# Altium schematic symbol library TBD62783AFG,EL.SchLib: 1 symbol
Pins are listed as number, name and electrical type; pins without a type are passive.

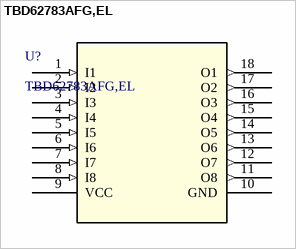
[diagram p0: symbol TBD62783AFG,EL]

## TBD62783AFG,EL
designator U?
Description; Manufacturer_Name: Toshiba Electronic Devices & Storage Corp.
footprint SOP18-P-375-1p27_TOS
pins: 1 I1 (in), 2 I2 (in), 3 I3 (in), 4 I4 (in), 5 I5 (in), 6 I6 (in), 7 I7 (in), 8 I8 (in), 9 VCC (power), 10 GND (power), 11 O8 (out), 12 O7 (out), 13 O6 (out), 14 O5 (out), 15 O4 (out), 16 O3 (out), 17 O2 (out), 18 O1 (out)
